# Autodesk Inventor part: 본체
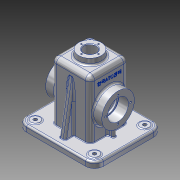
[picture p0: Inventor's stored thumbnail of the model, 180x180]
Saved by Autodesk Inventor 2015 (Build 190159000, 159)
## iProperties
Created: 2016-02
Part Number: 본체
Material: 알루미늄 6061
Document SubType Name: Modeling
Designer: Administrator
Density: 2.7 g/cm^3
Appearance: 알루미늄 - 평지
Mass: 847.465 g
Surface Area: 909.501 cm^2
Volume: 313.876 cm^3
Author: Administrator
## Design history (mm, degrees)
sketch "스케치1"
  geometry: L1 (65, 57.5)-(-65, 57.5); L2 (-65, 57.5)-(-65, -57.5); L3 (-65, -57.5)-(65, -57.5); L4 (65, -57.5)-(65, 57.5); L5 (65, 57.5)-(-65, -57.5); L6 (-65, 57.5)-(65, -57.5); 1 further point
  constraints: 12 end point, 2 midpoint, 2 parallel, 1 horizontal, 1 perpendicular
  dimensions: "d1" = 115 distance between parallel lines of L1 L3; "d2" = 130 distance between parallel lines of L2 L4
extrude "돌출1" new body sketch "스케치1" distance "d3" = 10; taper "d4" = 0 deg
sketch "스케치2"
  geometry: L1 (-60, -52.5)-(60, -52.5); L2 (60, -52.5)-(60, 52.5); L3 (60, 52.5)-(-60, 52.5); L4 (-60, 52.5)-(-60, -52.5); L5 (-60, -52.5)-(60, 52.5); L6 (60, -52.5)-(-60, 52.5); 1 further point
  constraints: 12 end point, 2 midpoint, 2 parallel, 1 horizontal, 1 perpendicular
  dimensions: "d5" = 105 distance between parallel lines of L1 L3; "d6" = 120 distance between parallel lines of L4 L2
extrude "돌출2" join sketch "스케치2" distance "d7" = 2; taper "d8" = 0 deg
sketch "스케치3"
  geometry: L1 (-32.5, -32.5)-(32.5, -32.5); L2 (32.5, -32.5)-(32.5, 32.5); L3 (32.5, 32.5)-(-32.5, 32.5); L4 (-32.5, 32.5)-(-32.5, -32.5); L5 (-32.5, -32.5)-(32.5, 32.5); L6 (32.5, -32.5)-(-32.5, 32.5); 1 further point
  constraints: 12 end point, 2 midpoint, 2 parallel, 1 horizontal, 1 perpendicular
  dimensions: "d9" = 65 distance between parallel lines of L2 L4; "d10" = 65 distance between parallel lines of L1 L3
extrude "돌출3" join sketch "스케치3" distance "d11" = 98; taper "d12" = 0 deg
sketch "스케치4"
  geometry: C1 r 20 at (0, 0); 1 further point
  constraints: 1 centre point, 1 coincident
  dimensions: "d13" = 40 diameter of C1
extrude "돌출4" join sketch "스케치4" distance "d14" = 10; taper "d15" = 0 deg
node "작업 평면1"
sketch "스케치8"
  geometry: L1 (-40.195, 43)-(110.128, 43); L2 (85, -12)-(-20, -12) reference; L3 (32.5, 0)-(32.5, 137.472); L4 (-25, 0)-(90, 0) reference; C1 r 27.5 at (32.5, 43); 1 further point
  constraints: 4 end point, 2 point on line, 1 centre point, 1 horizontal, 1 midpoint, 1 vertical
  dimensions: "d23" = 55 distance between parallel lines of L2 L1; "d24" = 55 diameter of C1
extrude "돌출6" join sketch "스케치8" distance "d25" = 95; taper "d26" = 0 deg
sketch "스케치6"
  geometry: L1 (-27.5, -27.5)-(27.5, -27.5); L2 (27.5, -27.5)-(27.5, 27.5); L3 (27.5, 27.5)-(-27.5, 27.5); L4 (-27.5, 27.5)-(-27.5, -27.5); L5 (-27.5, -27.5)-(27.5, 27.5); L6 (27.5, -27.5)-(-27.5, 27.5); 1 further point
  constraints: 12 end point, 2 midpoint, 2 parallel, 1 horizontal, 1 perpendicular
  dimensions: "d16" = 55 distance between parallel lines of L1 L3; "d17" = 55 distance between parallel lines of L4 L2
extrude "돌출5" cut sketch "스케치6" distance "d18" = 105; taper "d19" = 0 deg
node "작업 평면2"
sketch "스케치10"
  geometry: L1 (32.5, -32.5)-(-32.5, -32.5) reference; L2 (5, -32.5)-(-5, -32.5); L3 (-5, -32.5)-(-5, -47.5); L4 (-5, -47.5)-(5, -47.5); L5 (5, -47.5)-(5, -32.5); L6 (-65, -57.5)-(65, -57.5) reference; L7 (0, -63.602)-(0, 89.117); 1 further point
  constraints: 10 end point, 2 parallel, 2 point on line, 1 horizontal, 1 perpendicular, 1 vertical, 1 other
  dimensions: "d28" = 10 distance between parallel lines of L6 L4; "d29" = 10 distance between parallel lines of L5 L3
extrude "돌출7" join sketch "스케치10" stored distance "d30" = 95; taper "d31" = 0 deg
feature "면 기울기1" dims angle "d32" = 10 deg
sketch "스케치11"
  geometry: C1 r 10.5 at (0, 0); 1 further point
  constraints: 1 centre point, 1 coincident
  dimensions: "d33" = 21 diameter of C1
extrude "돌출8" cut sketch "스케치11" stored distance "d34" = 95; taper "d35" = 0 deg
fillet "모깎기1" dims "d36" = 3
sketch "스케치12"
  geometry: C1 r 27.5 at (0, 0) reference; C2 r 15 at (0, 0); 1 further point
  constraints: 1 centre point, 1 coincident
  dimensions: "d37" = 30 diameter of C2
extrude "돌출9" cut sketch "스케치12" stored distance "d38" = 95; taper "d39" = 0 deg
sketch "스케치13"
  geometry: C1 r 27.5 at (0, 0) reference; C2 r 17.5 at (0, 0); 1 further point
  constraints: 1 centre point, 1 coincident
  dimensions: "d40" = 35 diameter of C2
extrude "돌출10" cut sketch "스케치13" distance "d41" = 17; taper "d42" = 0 deg
fillet "모깎기2" dims "d43" = 15
sketch "스케치14"
  geometry: C1 r 7.5 at (-50, -42.5); C2 r 7.5 at (-50, 42.5); C3 r 7.5 at (50, 42.5); C4 r 7.5 at (50, -42.5); A1 r 15 centre (-50, 42.5) between (-50, 57.5) and (-65, 42.5) reference; A2 r 15 centre (-50, -42.5) between (-65, -42.5) and (-50, -57.5) reference; A3 r 15 centre (50, -42.5) between (50, -57.5) and (65, -42.5) reference; A4 r 15 centre (50, 42.5) between (65, 42.5) and (50, 57.5) reference; 1 further point
  constraints: 4 centre point, 4 coincident, 3 equal radius
  dimensions: "d44" = 15 diameter of C1
extrude "돌출11" join sketch "스케치14" distance "d45" = 1; taper "d46" = 0 deg
fillet "모깎기3" dims "d47" = 10
sketch "스케치15"
  geometry: A1 r 15 centre (100, -85) between (100, -100) and (115, -85) reference; A2 r 15 centre (0, -85) between (-15, -85) and (0, -100) reference; A3 r 15 centre (0, 0) between (0, 15) and (-15, 0) reference; A4 r 15 centre (100, 0) between (115, 0) and (100, 15) reference; 1 further point
hole "구멍1" sketch "스케치15" at (0, 0), (100, 0), (100, -85), (0, -85) diameter "d48" = 6; stored, may be unused: countersink angle "d52" = 90 deg, drill point angle "d54" = 118 deg; dims "d49" = 6, "d50" = 4, "d51" = 2, "d53" = 8
fillet "모깎기4" dims "d55" = 3
fillet "모깎기5" dims "d56" = 8
fillet "모깎기6" dims "d57" = 8
feature "면 기울기2" dims angle "d58" = 5 deg
fillet "모깎기7" dims "d59" = 3
fillet "모깎기8" dims "d60" = 3
sketch "스케치20"
  geometry: L1 (0, 0)-(49, 0) reference; L2 (21.5, 0)-(27.5, 0); L3 (27.5, 0)-(27.5, 17.968); L4 (27.5, 17.968)-(21.5, 17.968); L5 (21.5, 17.968)-(21.5, 0); L6 (24.5, -23.196)-(24.5, 40.328); 2 further points
  constraints: 10 end point, 2 parallel, 2 point on line, 1 horizontal, 1 midpoint, 1 perpendicular, 1 vertical, 1 other
  dimensions: "d93" = 6 distance between parallel lines of L5 L3; "d94" = 17.96798 distance between parallel lines of L1 L4
extrude "돌출12" join sketch "스케치20" distance "d95" = 10; taper "d96" = 0 deg
sketch "스케치16"
  geometry: 2 further points
  constraints: 1 vertical alignment
  dimensions: "d63" = 14.5 distance of point (0, 0) point (0, 14.5)
hole "구멍2" sketch "스케치16" at (0, 14.5) diameter "d64" = 2.459; stored, may be unused: countersink angle "d68" = 90 deg, drill point angle "d70" = 118 deg; dims "d65" = 7, "d66" = 4, "d67" = 2, "d69" = 9
sketch "스케치17"
  geometry: C1 r 17.5 at (0, 0) reference; 2 further points
  constraints: 1 vertical alignment
  dimensions: "d74" = 21 distance of C1.centre point (0, 21)
hole "구멍3" sketch "스케치17" at (0, 21) diameter "d75" = 3.242; stored, may be unused: countersink angle "d79" = 90 deg, drill point angle "d81" = 118 deg; dims "d76" = 8, "d77" = 4, "d78" = 2, "d80" = 10
fillet "모깎기11" dims "d85" = 0.3
chamfer "모따기1" distance "d86" = 1; stored, may be unused: second distance "d87" = 2, angle "d88" = 45 deg
sketch "스케치18"
  geometry: L1 (43.625, 18)-(5.375, 18) reference; L2 (-8, 0)-(-8, -90) reference; 3 further points
  constraints: 1 other
  dimensions: "d89" = 26 distance from line of L1 point (24.5, -8); "d90" = 32.5 distance from line of L2 point (24.5, -8)
feature "엠보싱1" sketch "스케치18" dims "d9" = 65, "d10" = 65, "d91" = 0.5, "d92" = 0
fillet "모깎기12" dims "d97" = 3
fillet "모깎기13" dims "d98" = 3
fillet "모깎기14" dims "d99" = 1
node "솔리드1"
mirror "대칭1"
mirror "대칭2"
mirror "대칭4"
pattern_circular "원형 패턴1" dims angle "d72" = 360 deg
pattern_circular "원형 패턴2" dims angle "d83" = 360 deg
mirror "대칭3"
other parameters: "d22" = 15, "d27" = -15
